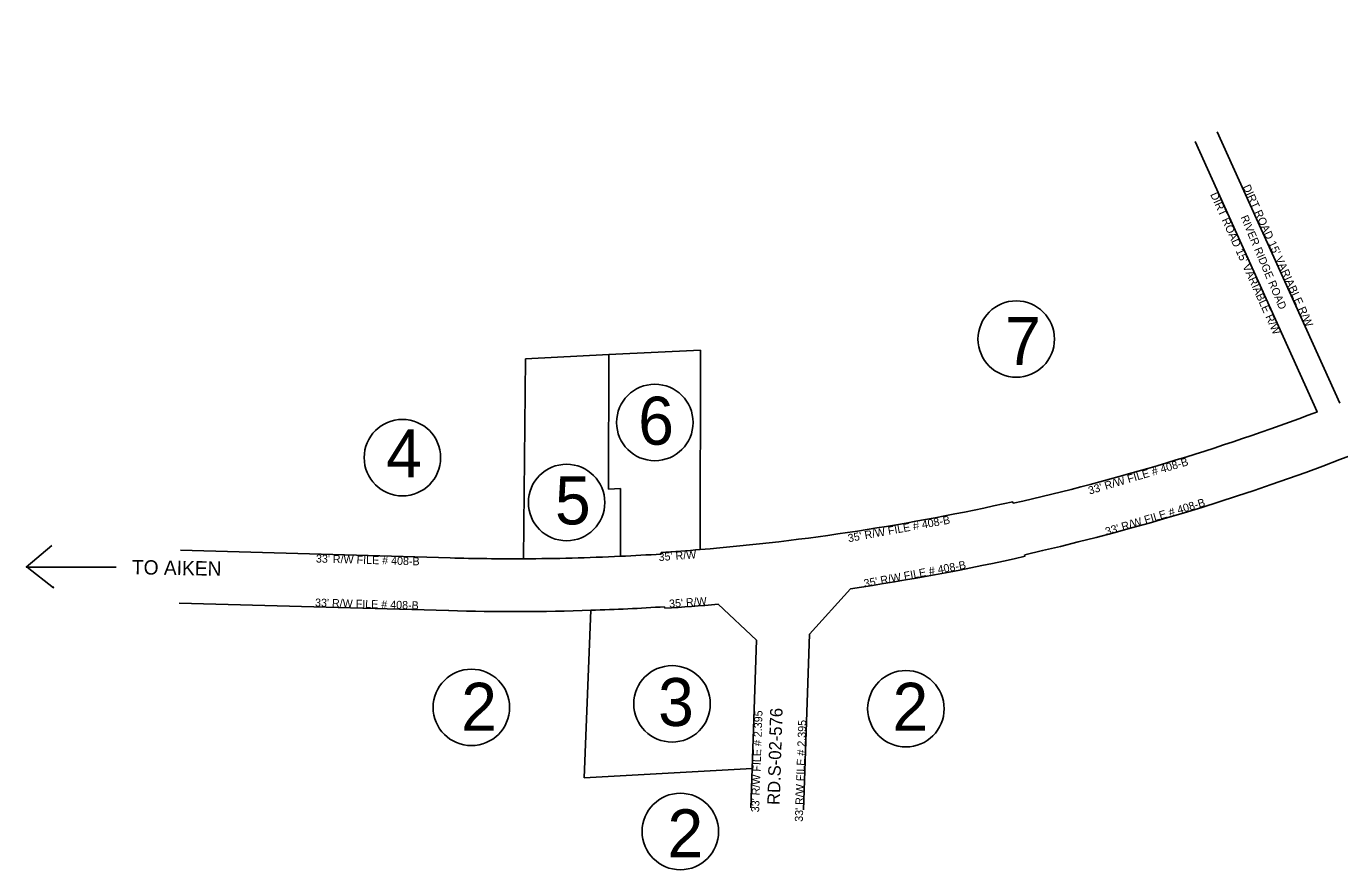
# Model space of a CAD drawing. Extents: x 50032 to 55703, y 49604 to 53496.
# Drawn here: x 50032 to 51673, y 49604 to 50659 of the extents above; entities that cross this region are included whole.
import ezdxf

# ---------------------------------------------------------------- set-up
doc = ezdxf.new("R2010")
doc.units = 0
doc.layers.add('Level 12', color=7, linetype='Continuous')
doc.layers.add('Level 25', color=7, linetype='Continuous')

msp = doc.modelspace()

# ---------------------------------------------------------------- linework, layer by layer
at = {"layer": 'Level 12'}
for p, q in [((51645.3, 50176.5), (51492.8, 50514.4)), ((51673.3, 50187.3), (51520.2, 50526.8)), ((50874.3, 50253.7), (50759.6, 50248)), ((50874.1, 50004.3), (50874.3, 50253.7)), ((50653.2, 49992.7), (50655.5, 50242.8)), ((50655.5, 50242.8), (50759.6, 50248)), ((50759.6, 50248), (50759.5, 50079.8)), ((50759.5, 50079.8), (50774.4, 50080.7)), ((50774.4, 49995.8), (50774.4, 50080.7)), ((51264.5, 50064.1), (51265, 50062.2)), ((50224.5, 50003.4), (50561.5, 49993.8)), ((50825.2, 49998.7), (50825, 50000.6)), ((51279.9, 49995.8), (51279.5, 49997.8)), ((51061.9, 49955.3), (51010.7, 49898.5)), ((50222.6, 49937.4), (50559.6, 49927.9)), ((50737.5, 49928.3), (50729.1, 49718.9)), ((50829.5, 49932.8), (50829.6, 49930.8)), ((50944.4, 49890.8), (50896.3, 49935.9)), ((50938.9, 49730.6), (50944.4, 49890.8)), ((51003.2, 49678.9), (51010.7, 49898.5)), ((50938.9, 49730.6), (50729.1, 49718.9)), ((50938.9, 49730.6), (50937.3, 49681.1))]:
    msp.add_line(p, q, dxfattribs=at)
for radius, start, end in [(2897.8, 282.7178, 311.6334), (2831.8, 282.7178, 290.7595), (2829.8, 274.7129, 282.7178), (2829.8, 273.7178, 274.7129), (2831.8, 268.3796, 270.2353), (2831.8, 270.2353, 272.6882), (2831.8, 272.6882, 273.7178), (2899.8, 278.3354, 282.7178), (2897.8, 268.3796, 271.8966), (2897.8, 271.8966, 273.7178), (2899.8, 273.7178, 275.0405)]:
    msp.add_arc((50641.6, 52824.5), radius, start, end, dxfattribs=at)
at = {"layer": 'Level 25'}
for points in [[(50144.2, 49982.3), (50032.9, 49982.3), (50031.7, 49982.3), (50063.5, 50009.3)], [(50032.9, 49982.3), (50065.9, 49956.6), (50064.7, 49957.9)]]:
    msp.add_lwpolyline(points, dxfattribs=at)
for centre in [(51269, 50267.5), (50817.3, 50163.2), (50501.8, 50119.2), (50707, 50063.1), (50838.8, 49811.3), (50588, 49806.9), (51131.1, 49805.2), (50849.2, 49651.7)]:
    msp.add_circle(centre, 47.8, dxfattribs=at)

# ---------------------------------------------------------------- texts
for s, height, rotation, p in [("DIRT ROAD 15' VARIABLE R/W", 10, 294.2826, (51511.2, 50448.3)), ("DIRT ROAD 15' VARIABLE R/W", 10, 294.2826, (51551.8, 50458)), ('RIVER RIDGE ROAD', 9.773, 292.8602, (51549.2, 50419.9)), ("33' R/W FILE # 408-B", 10, 16.609, (51360.7, 50072.9)), ("33' R/W FILE # 408-B", 10, 16.7224, (51381.9, 50021.7)), ("35' R/W FILE # 408-B", 10, 10.421, (51059.5, 50013.4)), ('TO AIKEN', 17.93, 358.9671, (50163.6, 49973.4)), ("33' R/W FILE # 408-B", 10, 358.3796, (50393.6, 49988.1)), ("35' R/W", 10, 4.3225, (50822.4, 49989.8)), ("35' R/W FILE # 408-B", 10, 10.6057, (51079.4, 49956.8)), ("33' R/W FILE # 408-B", 10, 358.3796, (50392.5, 49933.1)), ("33' R/W FILE # 408-B", 10, 358.3796, (50392.5, 49933.1)), ("35' R/W", 10, 4.494, (50835.5, 49931.5)), ("33' R/W FILE # 2.395", 10, 88.051, (50947.6, 49675.6)), ('RD.S-02-576', 15.55, 88.2913, (50973.4, 49684.7)), ("33' R/W FILE # 2.395", 10, 88.051, (51002.2, 49663.7)), ("33' R/W FILE # 2.395", 10, 88.051, (51002.2, 49663.7))]:
    msp.add_text(s, height=height, rotation=rotation, dxfattribs=at).set_placement(p)
for s, p in [('7', (51255.1, 50235.1)), ('6', (50796.5, 50135.4)), ('4', (50481.5, 50094.4)), ('5', (50692.5, 50035.7)), ('3', (50821.4, 49783.6)), ('2', (50575.3, 49777.7)), ('2', (51114.4, 49777.7)), ('2', (50833.1, 49619.4))]:
    msp.add_text(s, height=60, dxfattribs=at).set_placement(p)

doc.saveas('drawing.dxf')
